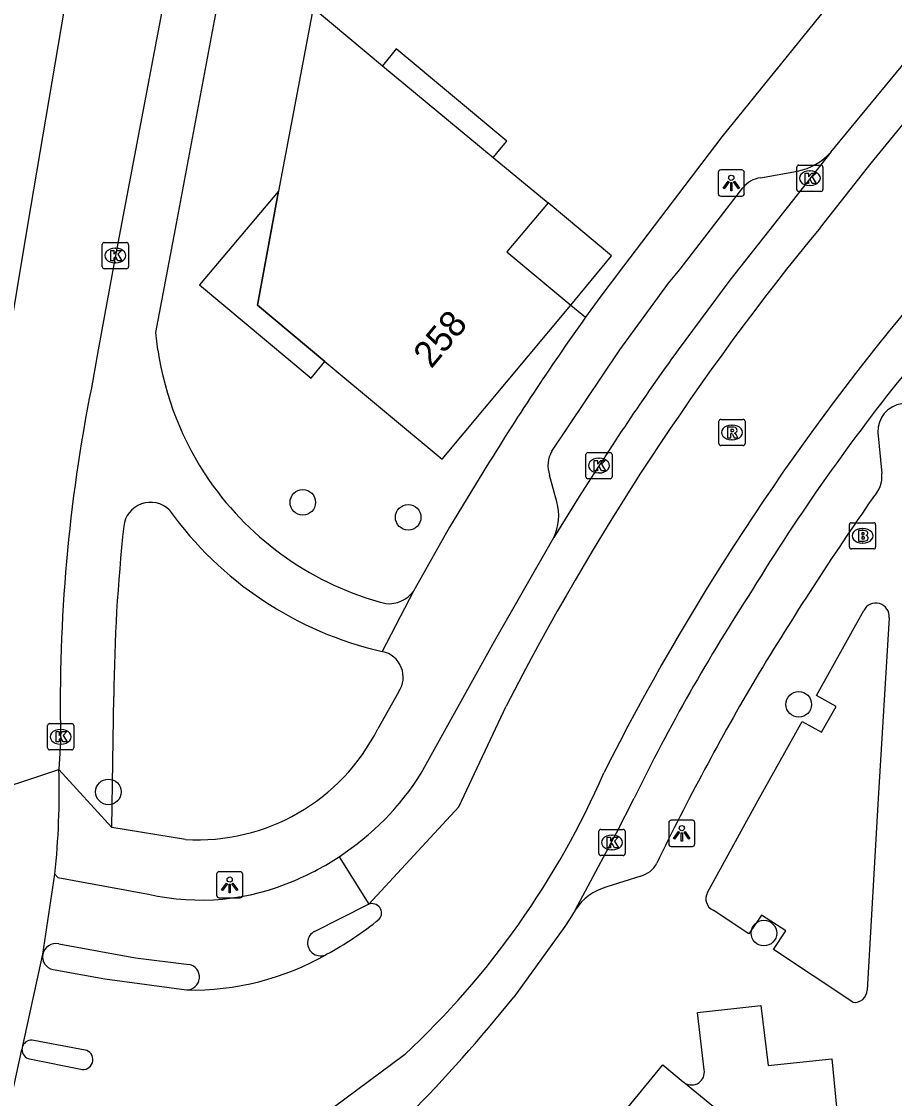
# Model space of a CAD drawing. Extents: x 160158 to 160921, y 381517 to 382041.
# Drawn here: x 160525.63 to 160559, y 381721.4 to 381762.55 of the extents above; entities that cross this region are included whole.
import ezdxf

# ---------------------------------------------------------------- set-up
doc = ezdxf.new("R2010")
doc.units = 0
for name, color, linetype in [('IMGEO_Boom', 7, 'Continuous'), ('IMGEO_Brandkraan', 7, 'Continuous'), ('IMGEO_Fietspad_open', 7, 'Continuous'), ('IMGEO_Groenvoorziening', 7, 'Continuous'), ('IMGEO_Kolk', 7, 'Continuous'), ('IMGEO_Lichtpunt', 7, 'Continuous'), ('IMGEO_Pand', 7, 'Continuous'), ('IMGEO_Pand_nummerreeks', 7, 'Continuous'), ('IMGEO_Pand_overbouw', 7, 'Continuous'), ('IMGEO_Rijbaan_lokaal_gesloten', 7, 'Continuous'), ('IMGEO_Rijbaan_lokaal_open', 7, 'Continuous'), ('IMGEO_Rijbaan_regionaal_gesloten', 7, 'Continuous'), ('IMGEO_Rioolput', 7, 'Continuous'), ('IMGEO_Voetpad_open', 7, 'Continuous')]:
    doc.layers.add(name, color=color, linetype=linetype)

msp = doc.modelspace()

# ---------------------------------------------------------------- linework, layer by layer
at = {"layer": 'IMGEO_Boom'}
for centre in [(160536.378, 381744.173), (160540.407, 381743.603), (160555.339, 381736.454), (160528.947, 381733.11), (160554.005, 381727.715)]:
    msp.add_circle(centre, 0.489, dxfattribs=at)
at = {"layer": 'IMGEO_Brandkraan'}
for p, q in [((160557.276, 381742.468), (160557.276, 381743.32)), ((160557.351, 381743.394), (160558.203, 381743.394)), ((160557.764, 381743.174), (160557.789, 381743.174)), ((160558.277, 381743.32), (160558.277, 381742.468)), ((160558.203, 381742.394), (160557.351, 381742.394)), ((160557.787, 381742.614), (160557.762, 381742.614))]:
    msp.add_line(p, q, dxfattribs=at)
for points in [[(160557.276, 381742.468), (160557.276, 381743.32)], [(160557.351, 381743.394), (160558.203, 381743.394)], [(160558.277, 381743.32), (160558.277, 381742.468)], [(160557.624, 381743.094), (160557.624, 381742.694), (160557.837, 381742.694)], [(160557.855, 381743.094), (160557.624, 381743.094)], [(160557.803, 381743.013), (160557.749, 381743.013), (160557.749, 381742.937)], [(160557.749, 381742.937), (160557.802, 381742.937)], [(160557.811, 381742.861), (160557.749, 381742.861), (160557.749, 381742.78)], [(160557.749, 381742.78), (160557.811, 381742.78)], [(160558.203, 381742.394), (160557.351, 381742.394)]]:
    msp.add_lwpolyline(points, dxfattribs=at)
for centre, radius, start, end in [((160557.353, 381743.318), 0.0765, 91.552, 178.448), ((160557.353, 381743.318), 0.0765, 91.552, 178.448), ((160558.201, 381743.318), 0.0765, 1.552, 88.448), ((160558.201, 381743.318), 0.0765, 1.552, 88.448), ((160557.804, 381742.975), 0.0379, 267.8285, 90.9355), ((160557.812, 381742.82), 0.0404, 269.8759, 90.5077), ((160557.859, 381742.949), 0.145, 59.4692, 91.5367), ((160557.884, 381742.996), 0.0922, 285.5137, 58.1501), ((160557.889, 381742.804), 0.105, 301.3115, 78.989), ((160557.353, 381742.47), 0.0765, 181.552, 268.448), ((160557.353, 381742.47), 0.0765, 181.552, 268.448), ((160557.843, 381742.945), 0.251, 268.6676, 293.5347), ((160558.201, 381742.47), 0.0765, 271.552, 358.448), ((160558.201, 381742.47), 0.0765, 271.552, 358.448)]:
    msp.add_arc(centre, radius, start, end, dxfattribs=at)
for centre, major_axis, ratio, start_param, end_param in [((160557.763, 381742.894), (-0.387, 0.002), 0.722429, 4.712389, 7.853982), ((160557.788, 381742.894), (-0.39, 0.002), 0.717154, 1.570796, 4.712389)]:
    msp.add_ellipse(centre, major_axis=major_axis, ratio=ratio, start_param=start_param, end_param=end_param, dxfattribs=at)
at = {"layer": 'IMGEO_Fietspad_open'}
for points in [[(160526.899, 381729.972), (160527.015, 381729.842), (160530.476, 381729.204)], [(160536.828, 381727.78), (160538.893, 381728.817)], [(160527.046, 381727.31), (160529.983, 381726.774), (160532.028, 381726.519)]]:
    msp.add_lwpolyline(points, dxfattribs=at)
for centre, radius, start, end in [((160531.939, 381739.506), 10.618, 292.9318, 303.2975), ((160532.483, 381737.962), 8.984, 257.0951, 293.576), ((160537.055, 381727.34), 0.495, 117.2662, 297.9867), ((160526.949, 381726.795), 0.524, 79.3116, 168.1119), ((160531.934, 381726.035), 0.493, 270.0875, 79.0373)]:
    msp.add_arc(centre, radius, start, end, dxfattribs=at)
at = {"layer": 'IMGEO_Groenvoorziening'}
msp.add_lwpolyline([(160546.621, 381751.714), (160547.187, 381751.244)], dxfattribs=at)
at = {"layer": 'IMGEO_Kolk'}
for p, q in [((160555.261, 381756.132), (160555.261, 381756.984)), ((160555.336, 381757.058), (160556.188, 381757.058)), ((160555.749, 381756.838), (160555.774, 381756.838)), ((160556.262, 381756.984), (160556.262, 381756.132)), ((160556.188, 381756.058), (160555.336, 381756.058)), ((160555.772, 381756.278), (160555.747, 381756.278)), ((160528.714, 381753.177), (160528.714, 381754.029)), ((160528.789, 381754.103), (160529.641, 381754.103)), ((160529.202, 381753.883), (160529.227, 381753.883)), ((160529.715, 381754.029), (160529.715, 381753.177)), ((160529.641, 381753.103), (160528.789, 381753.103)), ((160529.225, 381753.323), (160529.2, 381753.323)), ((160547.274, 381746.078), (160548.126, 381746.078)), ((160547.199, 381745.152), (160547.199, 381746.004)), ((160547.687, 381745.858), (160547.712, 381745.858)), ((160548.2, 381746.004), (160548.2, 381745.152)), ((160547.71, 381745.298), (160547.685, 381745.298)), ((160548.126, 381745.078), (160547.274, 381745.078)), ((160526.623, 381734.791), (160526.623, 381735.643)), ((160526.698, 381735.717), (160527.55, 381735.717)), ((160527.111, 381735.497), (160527.136, 381735.497)), ((160527.624, 381735.643), (160527.624, 381734.791)), ((160527.134, 381734.937), (160527.109, 381734.937)), ((160527.55, 381734.717), (160526.698, 381734.717)), ((160547.771, 381731.677), (160548.623, 381731.677)), ((160547.696, 381730.751), (160547.696, 381731.603)), ((160548.184, 381731.457), (160548.209, 381731.457)), ((160548.697, 381731.603), (160548.697, 381730.751)), ((160548.207, 381730.897), (160548.182, 381730.897)), ((160548.623, 381730.677), (160547.771, 381730.677))]:
    msp.add_line(p, q, dxfattribs=at)
for points in [[(160555.261, 381756.132), (160555.261, 381756.984)], [(160555.336, 381757.058), (160556.188, 381757.058)], [(160555.582, 381756.758), (160555.705, 381756.758), (160555.705, 381756.607), (160555.835, 381756.758), (160555.999, 381756.758), (160555.853, 381756.607), (160556.006, 381756.358), (160555.854, 381756.358), (160555.769, 381756.522), (160555.705, 381756.455), (160555.705, 381756.358), (160555.582, 381756.358), (160555.582, 381756.758)], [(160556.262, 381756.984), (160556.262, 381756.132)], [(160556.188, 381756.058), (160555.336, 381756.058)], [(160528.714, 381753.177), (160528.714, 381754.029)], [(160528.789, 381754.103), (160529.641, 381754.103)], [(160529.715, 381754.029), (160529.715, 381753.177)], [(160529.035, 381753.803), (160529.158, 381753.803), (160529.158, 381753.652), (160529.288, 381753.803), (160529.452, 381753.803), (160529.306, 381753.652), (160529.459, 381753.403), (160529.307, 381753.403), (160529.222, 381753.567), (160529.158, 381753.5), (160529.158, 381753.403), (160529.035, 381753.403), (160529.035, 381753.803)], [(160529.641, 381753.103), (160528.789, 381753.103)], [(160547.274, 381746.078), (160548.126, 381746.078)], [(160547.199, 381745.152), (160547.199, 381746.004)], [(160547.52, 381745.778), (160547.643, 381745.778), (160547.643, 381745.627), (160547.773, 381745.778), (160547.937, 381745.778), (160547.791, 381745.627), (160547.944, 381745.378), (160547.792, 381745.378), (160547.707, 381745.542), (160547.643, 381745.475), (160547.643, 381745.378), (160547.52, 381745.378), (160547.52, 381745.778)], [(160548.2, 381746.004), (160548.2, 381745.152)], [(160548.126, 381745.078), (160547.274, 381745.078)], [(160526.623, 381734.791), (160526.623, 381735.643)], [(160526.698, 381735.717), (160527.55, 381735.717)], [(160526.944, 381735.417), (160527.067, 381735.417), (160527.067, 381735.266), (160527.197, 381735.417), (160527.361, 381735.417), (160527.215, 381735.266), (160527.368, 381735.017), (160527.216, 381735.017), (160527.131, 381735.181), (160527.067, 381735.114), (160527.067, 381735.017), (160526.944, 381735.017), (160526.944, 381735.417)], [(160527.624, 381735.643), (160527.624, 381734.791)], [(160527.55, 381734.717), (160526.698, 381734.717)], [(160547.771, 381731.677), (160548.623, 381731.677)], [(160547.696, 381730.751), (160547.696, 381731.603)], [(160548.017, 381731.377), (160548.14, 381731.377), (160548.14, 381731.226), (160548.27, 381731.377), (160548.434, 381731.377), (160548.288, 381731.226), (160548.441, 381730.977), (160548.289, 381730.977), (160548.204, 381731.141), (160548.14, 381731.074), (160548.14, 381730.977), (160548.017, 381730.977), (160548.017, 381731.377)], [(160548.697, 381731.603), (160548.697, 381730.751)], [(160548.623, 381730.677), (160547.771, 381730.677)]]:
    msp.add_lwpolyline(points, dxfattribs=at)
for centre, start, end in [((160555.338, 381756.982), 91.552, 178.448), ((160555.338, 381756.982), 91.552, 178.448), ((160556.186, 381756.982), 1.552, 88.448), ((160556.186, 381756.982), 1.552, 88.448), ((160555.338, 381756.134), 181.552, 268.448), ((160555.338, 381756.134), 181.552, 268.448), ((160556.186, 381756.134), 271.552, 358.448), ((160556.186, 381756.134), 271.552, 358.448), ((160528.791, 381754.027), 91.552, 178.448), ((160528.791, 381754.027), 91.552, 178.448), ((160529.639, 381754.027), 1.552, 88.448), ((160529.639, 381754.027), 1.552, 88.448), ((160528.791, 381753.179), 181.552, 268.448), ((160528.791, 381753.179), 181.552, 268.448), ((160529.639, 381753.179), 271.552, 358.448), ((160529.639, 381753.179), 271.552, 358.448), ((160547.276, 381746.002), 91.552, 178.448), ((160547.276, 381746.002), 91.552, 178.448), ((160548.124, 381746.002), 1.552, 88.448), ((160548.124, 381746.002), 1.552, 88.448), ((160547.276, 381745.154), 181.552, 268.448), ((160547.276, 381745.154), 181.552, 268.448), ((160548.124, 381745.154), 271.552, 358.448), ((160548.124, 381745.154), 271.552, 358.448), ((160526.7, 381735.641), 91.552, 178.448), ((160526.7, 381735.641), 91.552, 178.448), ((160527.548, 381735.641), 1.552, 88.448), ((160527.548, 381735.641), 1.552, 88.448), ((160526.7, 381734.793), 181.552, 268.448), ((160526.7, 381734.793), 181.552, 268.448), ((160527.548, 381734.793), 271.552, 358.448), ((160527.548, 381734.793), 271.552, 358.448), ((160547.773, 381731.601), 91.552, 178.448), ((160547.773, 381731.601), 91.552, 178.448), ((160548.621, 381731.601), 1.552, 88.448), ((160548.621, 381731.601), 1.552, 88.448), ((160547.773, 381730.753), 181.552, 268.448), ((160547.773, 381730.753), 181.552, 268.448), ((160548.621, 381730.753), 271.552, 358.448), ((160548.621, 381730.753), 271.552, 358.448)]:
    msp.add_arc(centre, 0.0765, start, end, dxfattribs=at)
for centre, major_axis, ratio, start_param, end_param in [((160555.748, 381756.558), (-0.387, 0.002), 0.722429, 4.712389, 7.853982), ((160555.773, 381756.558), (-0.39, 0.002), 0.717154, 1.570796, 4.712389), ((160529.201, 381753.603), (-0.387, 0.002), 0.722429, 4.712389, 7.853982), ((160529.226, 381753.603), (-0.39, 0.002), 0.717154, 1.570796, 4.712389), ((160547.686, 381745.578), (-0.387, 0.002), 0.722429, 4.712389, 7.853982), ((160547.711, 381745.578), (-0.39, 0.002), 0.717154, 1.570796, 4.712389), ((160527.11, 381735.217), (-0.387, 0.002), 0.722429, 4.712389, 7.853982), ((160527.135, 381735.217), (-0.39, 0.002), 0.717154, 1.570796, 4.712389), ((160548.183, 381731.177), (-0.387, 0.002), 0.722429, 4.712389, 7.853982), ((160548.208, 381731.177), (-0.39, 0.002), 0.717154, 1.570796, 4.712389)]:
    msp.add_ellipse(centre, major_axis=major_axis, ratio=ratio, start_param=start_param, end_param=end_param, dxfattribs=at)
at = {"layer": 'IMGEO_Lichtpunt'}
for p, q in [((160552.261, 381756.779), (160552.261, 381755.972)), ((160552.261, 381756.779), (160552.261, 381755.972)), ((160553.163, 381756.874), (160552.355, 381756.874)), ((160553.163, 381756.874), (160552.355, 381756.874)), ((160553.257, 381755.972), (160553.257, 381756.779)), ((160553.257, 381755.972), (160553.257, 381756.779)), ((160552.355, 381755.878), (160553.163, 381755.878)), ((160552.355, 381755.878), (160553.163, 381755.878)), ((160550.369, 381731.929), (160550.369, 381731.122)), ((160550.369, 381731.929), (160550.369, 381731.122)), ((160551.271, 381732.024), (160550.463, 381732.024)), ((160551.271, 381732.024), (160550.463, 381732.024)), ((160551.365, 381731.122), (160551.365, 381731.929)), ((160551.365, 381731.122), (160551.365, 381731.929)), ((160550.463, 381731.028), (160551.271, 381731.028)), ((160550.463, 381731.028), (160551.271, 381731.028)), ((160533.986, 381730.058), (160533.178, 381730.058)), ((160533.986, 381730.058), (160533.178, 381730.058)), ((160533.084, 381729.963), (160533.084, 381729.156)), ((160533.084, 381729.963), (160533.084, 381729.156)), ((160534.08, 381729.156), (160534.08, 381729.963)), ((160534.08, 381729.156), (160534.08, 381729.963)), ((160533.178, 381729.062), (160533.986, 381729.062)), ((160533.178, 381729.062), (160533.986, 381729.062))]:
    msp.add_line(p, q, dxfattribs=at)
for points in [[(160552.635, 381756.443), (160552.674, 381756.415), (160552.486, 381756.153), (160552.448, 381756.18), (160552.635, 381756.443)], [(160552.737, 381756.395), (160552.784, 381756.395), (160552.784, 381756.073), (160552.737, 381756.073), (160552.737, 381756.395)], [(160552.847, 381756.415), (160552.885, 381756.442), (160553.072, 381756.18), (160553.033, 381756.152), (160552.847, 381756.415)], [(160550.743, 381731.593), (160550.782, 381731.565), (160550.594, 381731.303), (160550.556, 381731.33), (160550.743, 381731.593)], [(160550.845, 381731.545), (160550.892, 381731.545), (160550.892, 381731.223), (160550.845, 381731.223), (160550.845, 381731.545)], [(160550.955, 381731.565), (160550.993, 381731.592), (160551.18, 381731.33), (160551.141, 381731.302), (160550.955, 381731.565)], [(160533.458, 381729.627), (160533.497, 381729.599), (160533.309, 381729.337), (160533.271, 381729.364), (160533.458, 381729.627)], [(160533.56, 381729.579), (160533.607, 381729.579), (160533.607, 381729.257), (160533.56, 381729.257), (160533.56, 381729.579)], [(160533.67, 381729.599), (160533.708, 381729.626), (160533.895, 381729.364), (160533.856, 381729.336), (160533.67, 381729.599)]]:
    msp.add_lwpolyline(points, dxfattribs=at)
for centre in [(160552.76, 381756.577), (160550.868, 381731.727), (160533.583, 381729.761)]:
    msp.add_circle(centre, 0.0994, dxfattribs=at)
for centre, start, end in [((160552.355, 381756.779), 90, 180), ((160552.355, 381756.779), 90, 180), ((160553.163, 381756.779), 0, 90), ((160553.163, 381756.779), 0, 90), ((160552.355, 381755.972), 180, 270), ((160552.355, 381755.972), 180, 270), ((160553.163, 381755.972), 270, 0), ((160553.163, 381755.972), 270, 360), ((160550.463, 381731.929), 90, 180), ((160550.463, 381731.929), 90, 180), ((160551.271, 381731.929), 0, 90), ((160551.271, 381731.929), 0, 90), ((160550.463, 381731.122), 180, 270), ((160550.463, 381731.122), 180, 270), ((160551.271, 381731.122), 270, 0), ((160551.271, 381731.122), 270, 360), ((160533.178, 381729.963), 90, 180), ((160533.178, 381729.963), 90, 180), ((160533.986, 381729.963), 0, 90), ((160533.986, 381729.963), 0, 90), ((160533.178, 381729.156), 180, 270), ((160533.178, 381729.156), 180, 270), ((160533.986, 381729.156), 270, 0), ((160533.986, 381729.156), 270, 360)]:
    msp.add_arc(centre, 0.0946, start, end, dxfattribs=at)
at = {"layer": 'IMGEO_Pand'}
for points in [[(160536.769, 381763.076), (160535.455, 381756.063), (160534.647, 381751.702), (160537.22, 381749.558), (160541.708, 381745.82), (160546.621, 381751.714)], [(160536.769, 381763.076), (160539.423, 381760.856), (160543.658, 381757.346), (160545.757, 381755.618), (160544.18, 381753.74), (160546.621, 381751.714)]]:
    msp.add_lwpolyline(points, dxfattribs=at)
at = {"layer": 'IMGEO_Pand_overbouw'}
for points in [[(160539.423, 381760.856), (160543.658, 381757.346), (160544.179, 381757.981), (160539.946, 381761.505)], [(160537.22, 381749.558), (160534.647, 381751.702), (160535.455, 381756.063), (160532.435, 381752.487), (160536.695, 381748.923)], [(160546.621, 381751.714), (160548.178, 381753.589), (160545.757, 381755.618), (160544.18, 381753.74)]]:
    msp.add_lwpolyline(points, close=True, dxfattribs=at)
at = {"layer": 'IMGEO_Rijbaan_lokaal_gesloten'}
for points in [[(160556.164, 381754.68), (160558.112, 381757.129), (160560.755, 381760.365), (160581.539, 381785.212), (160597.19, 381803.934)], [(160556.569, 381757.556), (160561.758, 381763.877), (160562.011, 381764.214)], [(160556.569, 381757.556), (160552.708, 381752.669), (160550.722, 381750)], [(160546.946, 381744.393), (160545.97, 381742.825)], [(160540.908, 381733.824), (160543.709, 381738.866), (160545.97, 381742.825)], [(160538.897, 381728.821), (160542.337, 381732.544), (160544.152, 381736.39)], [(160546.789, 381728.587), (160548.37, 381731.543), (160549.042, 381732.866)], [(160537.768, 381730.631), (160538.897, 381728.821)], [(160546.789, 381728.587), (160546.585, 381728.258), (160546.4, 381727.966), (160544.441, 381725.267)], [(160540.266, 381723.067), (160537.539, 381721.041), (160536.719, 381720.581), (160535.822, 381720.136), (160534.947, 381719.768), (160533.48, 381719.467), (160532.447, 381719.456)]]:
    msp.add_lwpolyline(points, dxfattribs=at)
for centre, radius, start, end in [((160635.278, 381689.632), 102.422, 140.57288, 152.83712), ((160632.422, 381691.188), 94.687, 140.2702, 153.23003), ((160638.25, 381686.98), 107.855, 144.24611, 147.83778), ((160621.002, 381699.491), 79.102, 141.03142, 148.50079), ((160616.65, 381699.761), 75.278, 146.94466, 153.91056), ((160531.933, 381739.51), 10.625, 303.3136, 327.6454), ((160518.343, 381746.652), 32.201, 312.9091, 336.5467), ((160498, 381762.545), 59.552, 315.38401, 321.24578)]:
    msp.add_arc(centre, radius, start, end, dxfattribs=at)
at = {"layer": 'IMGEO_Rijbaan_lokaal_open'}
for points in [[(160538.893, 381728.817), (160538.897, 381728.821)], [(160538.898, 381728.819), (160538.893, 381728.817)], [(160526.829, 381726.321), (160528.804, 381725.967), (160531.935, 381725.542)], [(160528.056, 381723.247), (160526.092, 381723.611)], [(160525.936, 381722.907), (160527.953, 381722.503)], [(160546.247, 381717.93), (160550.145, 381722.678), (160550.918, 381722.034), (160550.931, 381722.022), (160550.945, 381722.011)], [(160557.472, 381716.661), (160550.945, 381722.011)]]:
    msp.add_lwpolyline(points, dxfattribs=at)
for centre, radius, start, end in [((160539.025, 381728.479), 0.363, 319.9746, 110.5313), ((160530.732, 381738.927), 13.694, 298.5962, 308.7446), ((160526.935, 381726.816), 0.506, 170.1076, 257.9514), ((160532.16, 381735.861), 10.322, 268.7515, 299.784), ((160526.004, 381723.258), 0.363, 76.0149, 155.3473), ((160526.004, 381723.262), 0.362, 179.4287, 259.2022), ((160527.979, 381722.879), 0.376, 266.0209, 78.2151)]:
    msp.add_arc(centre, radius, start, end, dxfattribs=at)
at = {"layer": 'IMGEO_Rijbaan_regionaal_gesloten'}
for points in [[(160534.195, 381779.861), (160532.282, 381769.787), (160531.658, 381766.473), (160531.031, 381763.137), (160529.214, 381753.603), (160528.561, 381750), (160528.299, 381748.554)], [(160527.375, 381763.707), (160525.853, 381754.764), (160525.07, 381750), (160524.88, 381748.845)], [(160527.122, 381735.217), (160527.053, 381733.968)], [(160523.809, 381732.9), (160527.053, 381733.968)], [(160526.436, 381726.903), (160526.899, 381729.972)], [(160525.674, 381723.41), (160526.436, 381726.903)], [(160524.887, 381719.791), (160525.642, 381723.266)]]:
    msp.add_lwpolyline(points, dxfattribs=at)
for centre, radius, start, end in [((160588.028, 381736.562), 60.921, 168.64783, 181.26551), ((160498.088, 381733.083), 28.978, 353.8365, 1.7495), ((160526.02, 381723.258), 0.378, 156.2165, 178.7259)]:
    msp.add_arc(centre, radius, start, end, dxfattribs=at)
at = {"layer": 'IMGEO_Rioolput'}
for p, q in [((160552.283, 381746.418), (160552.283, 381747.27)), ((160552.358, 381747.344), (160553.21, 381747.344)), ((160553.284, 381747.27), (160553.284, 381746.418)), ((160552.771, 381747.124), (160552.796, 381747.124)), ((160552.794, 381746.564), (160552.769, 381746.564)), ((160553.21, 381746.344), (160552.358, 381746.344))]:
    msp.add_line(p, q, dxfattribs=at)
for points in [[(160552.283, 381746.418), (160552.283, 381747.27)], [(160552.358, 381747.344), (160553.21, 381747.344)], [(160553.284, 381747.27), (160553.284, 381746.418)], [(160552.872, 381747.042), (160552.62, 381747.044), (160552.62, 381746.644)], [(160552.798, 381746.963), (160552.744, 381746.963), (160552.744, 381746.882)], [(160552.744, 381746.882), (160552.796, 381746.882)], [(160552.62, 381746.644), (160552.744, 381746.644), (160552.744, 381746.806), (160552.755, 381746.806)], [(160552.802, 381746.777), (160552.873, 381746.644), (160553.013, 381746.644), (160552.948, 381746.77)], [(160553.21, 381746.344), (160552.358, 381746.344)]]:
    msp.add_lwpolyline(points, dxfattribs=at)
for centre, radius, start, end in [((160552.36, 381747.268), 0.0765, 91.552, 178.448), ((160552.36, 381747.268), 0.0765, 91.552, 178.448), ((160553.208, 381747.268), 0.0765, 1.552, 88.448), ((160553.208, 381747.268), 0.0765, 1.552, 88.448), ((160552.78, 381747.071), 0.19, 274.7715, 282.9687), ((160552.804, 381746.867), 0.0964, 77.0061, 93.1865), ((160552.818, 381746.924), 0.0378, 276.6634, 79.6772), ((160552.871, 381746.932), 0.109, 350.3612, 89.416), ((160552.869, 381746.932), 0.112, 277.5842, 350.9817), ((160552.754, 381746.753), 0.0533, 26.0293, 88.6989), ((160552.853, 381746.717), 0.108, 29.5134, 73.7905), ((160552.36, 381746.42), 0.0765, 181.552, 268.448), ((160552.36, 381746.42), 0.0765, 181.552, 268.448), ((160553.208, 381746.42), 0.0765, 271.552, 358.448), ((160553.208, 381746.42), 0.0765, 271.552, 358.448)]:
    msp.add_arc(centre, radius, start, end, dxfattribs=at)
for centre, major_axis, ratio, start_param, end_param in [((160552.77, 381746.844), (-0.387, 0.002), 0.722429, 4.712389, 7.853982), ((160552.795, 381746.844), (-0.39, 0.002), 0.717154, 1.570796, 4.712389)]:
    msp.add_ellipse(centre, major_axis=major_axis, ratio=ratio, start_param=start_param, end_param=end_param, dxfattribs=at)
at = {"layer": 'IMGEO_Voetpad_open'}
for points in [[(160569.786, 381785.666), (160572.924, 381783.093), (160566.256, 381774.976), (160559.232, 381766.417), (160556.812, 381763.555), (160556.143, 381762.763), (160552.4, 381758.139), (160548.643, 381753.199), (160547.737, 381752.007), (160547.187, 381751.244)], [(160530.838, 381750), (160530.76, 381750.659), (160531.549, 381754.827), (160533.001, 381762.573), (160535.155, 381773.997), (160536.414, 381780.659)], [(160553.871, 381756.578), (160555.296, 381756.832)], [(160545.901, 381746.126), (160548.495, 381750), (160550.361, 381752.545), (160550.801, 381753.081), (160553.198, 381756.188)], [(160558.366, 381746.845), (160558.508, 381745.28)], [(160543.304, 381745.379), (160541.983, 381743.231), (160540.611, 381740.781)], [(160546.091, 381744.193), (160545.815, 381745.216)], [(160540.611, 381740.781), (160539.413, 381738.471)], [(160551.845, 381729.26), (160553.785, 381732.792), (160555.472, 381735.795), (160556.207, 381735.389), (160556.763, 381736.375), (160556.011, 381736.788), (160557.825, 381740.047)], [(160558.795, 381739.761), (160558.374, 381732.854)], [(160529.082, 381731.747), (160529.151, 381736.75)], [(160540.038, 381736.922), (160539.248, 381735.524)], [(160529.082, 381731.747), (160527.053, 381733.968)], [(160558.374, 381732.854), (160557.948, 381725.533)], [(160531.892, 381731.292), (160529.082, 381731.747)], [(160549.297, 381729.89), (160548.003, 381729.479)], [(160557.404, 381725.071), (160554.369, 381727.087), (160554.849, 381727.795), (160553.916, 381728.395), (160553.427, 381727.691), (160552.063, 381728.596)], [(160551.721, 381722.49), (160551.466, 381724.684), (160553.891, 381724.954), (160554.167, 381722.654), (160556.607, 381722.907), (160557.151, 381717.248)], [(160550.945, 381722.011), (160550.959, 381722.001), (160550.974, 381721.991)]]:
    msp.add_lwpolyline(points, dxfattribs=at)
for centre, radius, start, end in [((160554.856, 381759.087), 2.297, 281.0424, 318.2144), ((160554.037, 381755.516), 1.075, 98.8848, 141.2994), ((160627.441, 381693.893), 98.64, 144.44965, 148.5362), ((160542.505, 381751.716), 11.792, 188.3662, 214.6331), ((160559.408, 381746.901), 1.044, 96.8317, 183.0635), ((160546.801, 381745.582), 1.052, 148.8474, 200.3551), ((160557.409, 381745.154), 1.106, 314.2629, 6.5244), ((160542.491, 381751.709), 11.777, 214.6422, 255.5732), ((160530.557, 381743.145), 1.03, 45.9388, 173.6939), ((160544.229, 381743.668), 1.934, 334.1528, 15.7378), ((160665.269, 381669.95), 130.403, 145.20587, 148.81771), ((160542.511, 381751.955), 13.835, 215.6825, 257.0609), ((160595.465, 381736.123), 66.317, 173.82346, 179.45807), ((160539.652, 381741.494), 1.195, 265.4295, 323.3601), ((160558.282, 381739.81), 0.515, 354.542, 152.6021), ((160539.22, 381737.493), 0.997, 325.0805, 78.8663), ((160642.221, 381685.451), 102.668, 149.55897, 154.04706), ((160532.352, 381739.002), 7.724, 266.5877, 333.2371), ((160549.033, 381730.842), 0.988, 285.5138, 332.2625), ((160548.521, 381727.501), 2.045, 104.6892, 147.9248), ((160552.256, 381729.027), 0.472, 150.4333, 245.9181), ((160557.478, 381725.536), 0.47, 261.0041, 359.6761), ((160551.242, 381722.398), 0.487, 236.5875, 10.8987)]:
    msp.add_arc(centre, radius, start, end, dxfattribs=at)

# ---------------------------------------------------------------- texts
at = {"layer": 'IMGEO_Pand_nummerreeks'}
msp.add_text('258', height=1, rotation=50.1891, dxfattribs=at).set_placement((160541.291, 381749.255))

doc.saveas('drawing.dxf')
